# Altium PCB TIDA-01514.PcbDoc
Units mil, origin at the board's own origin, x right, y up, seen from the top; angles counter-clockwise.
Board outline 2800 x 2500 mil, 2 copper layers (Top Layer, Bottom Layer), stack 61.6 mil thick; 63 components, 22 nets, 133 pads, 71 vias.
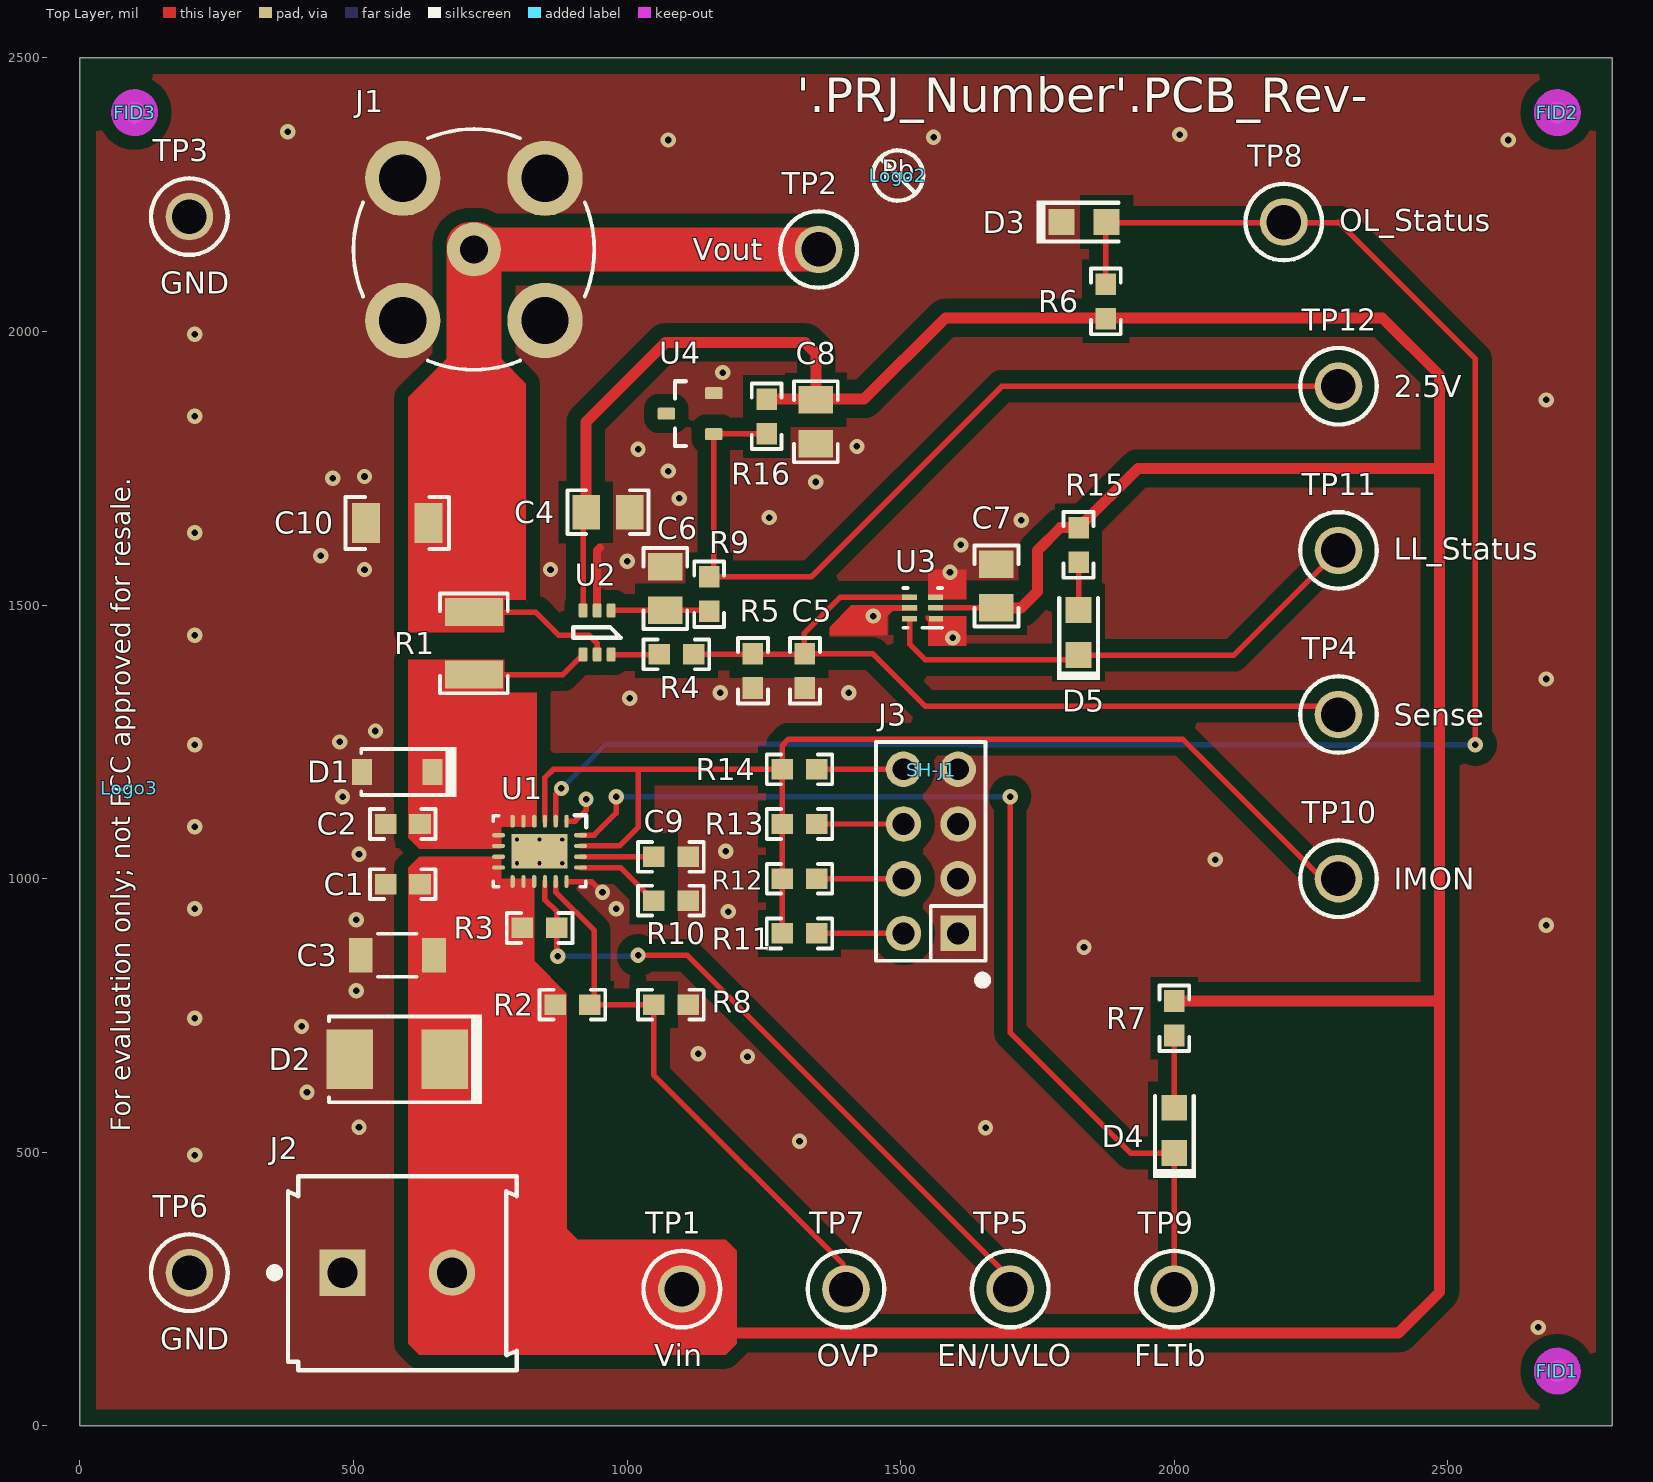
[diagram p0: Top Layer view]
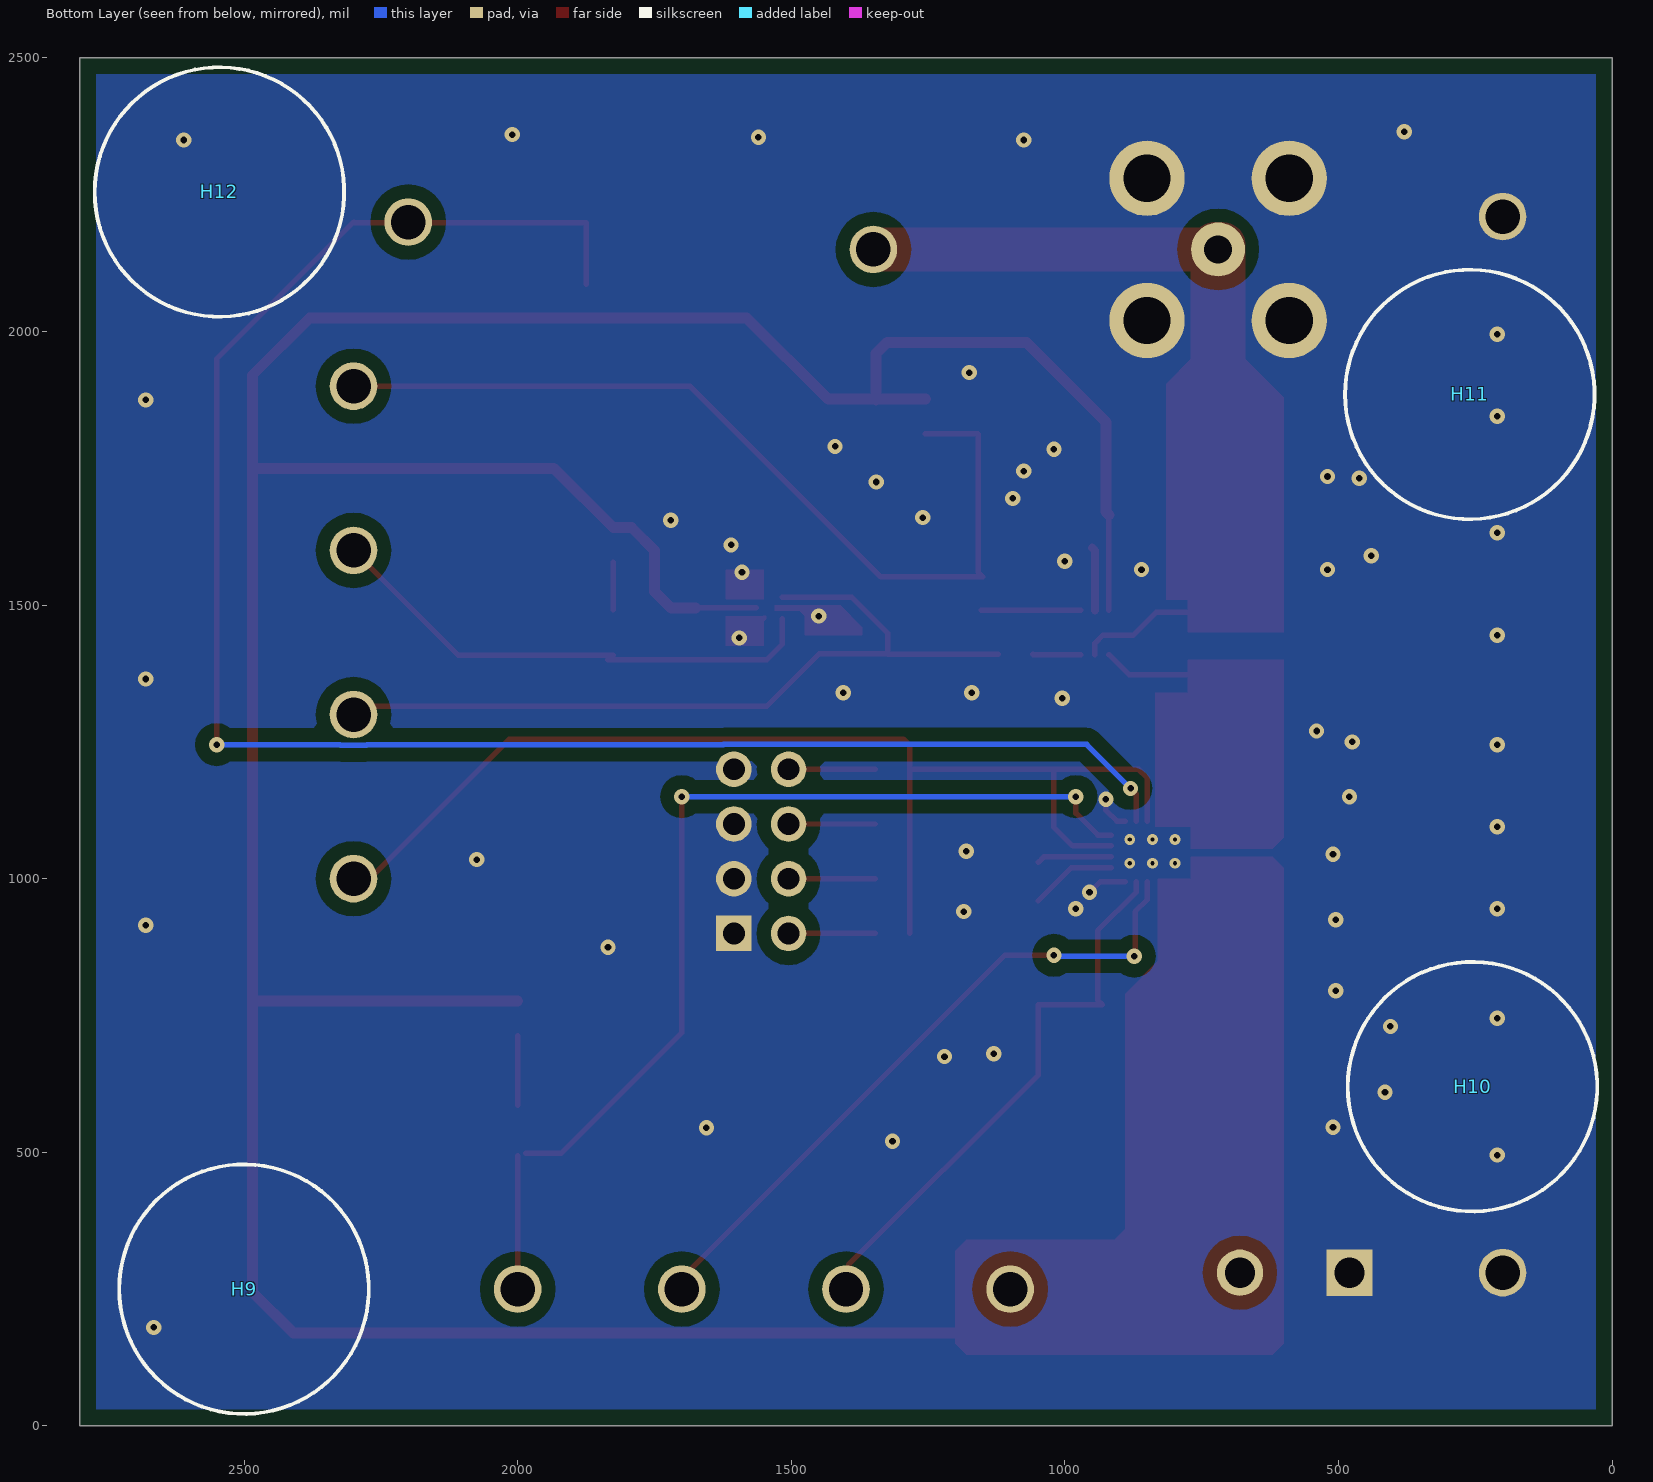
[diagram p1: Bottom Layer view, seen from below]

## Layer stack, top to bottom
Top Solder: solder mask 0.4, Solder Resist, Dk 3.5
Top Layer: signal copper 2.8
Dielectric1: core 56, FR-4, Dk 4.8
Bottom Layer: signal copper 2.8
Bottom Solder: solder mask 0.4, Solder Resist, Dk 3.5

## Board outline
0,0 0,2500 2800,2500 2800,0

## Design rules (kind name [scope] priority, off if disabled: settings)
AcuteAngle [All] p1: minimum=4.50000000000000E+0001 checktracksonly=FALSE
AssemblyTestPointUsage [All] p1: valid=2
BoardOutlineClearance BoardOutlineClearance_MountingHoles [OnCopper and InComponentClass('Mounting Holes')] p1: gap=40 ignorepadtopadclearanceinfootprint=FALSE
BoardOutlineClearance BoardOutlineClearance_Poly [OnCopper and IsPoly] p2: gap=25 ignorepadtopadclearanceinfootprint=FALSE
BoardOutlineClearance [OnCopper and Not InComponentClass('Logo') and not InComponentClass('FiducialMark') and not InRegion(1000,500,4000,800) and not InPoly] p3: gap=75 ignorepadtopadclearanceinfootprint=FALSE
Clearance Clearance_Keepouts [((IsTrack Or IsArc) And Not InPoly) And IsFree and IsKeepOut vs ((IsTrack Or IsArc) And Not InPoly) And IsFree and IsKeepOut] p1: gap=0 ignorepadtopadclearanceinfootprint=FALSE
Clearance Clearance_Poly [InPolygon] p2: gap=25 ignorepadtopadclearanceinfootprint=FALSE except(0: Arc-Hole Track-Hole SMDPad-Hole THPad-Hole Via-Hole Fill-Hole Poly-Hole Region-Hole Text-Hole)
Clearance Clearance_FiducialMark [IsKeepOut and InComponentClass('FiducialMark') vs IsPad and InComponentClass('FiducialMark')] p3: gap=0 ignorepadtopadclearanceinfootprint=FALSE
Clearance [All] p4: gap=7.87 ignorepadtopadclearanceinfootprint=FALSE except(0: Arc-Hole Track-Hole SMDPad-Hole THPad-Hole Via-Hole Fill-Hole Poly-Hole Region-Hole Text-Hole)
ComponentClearance ComponentClearance_MountingHoles_FiducialMarks [InComponentClass('Mounting Holes') vs InComponentClass('FiducialMark')] p1: gap=50 collisioncheckmode=3 verticalgap=10 showdistances=FALSE
ComponentClearance ComponentClearance_Shunt [InComponentClass('Header') vs InComponentClass('Shunt')] p2: gap=0 collisioncheckmode=3 verticalgap=0 showdistances=FALSE
ComponentClearance ComponentClearance_Logo [InComponentClass('Logo')] p3: gap=50 collisioncheckmode=3 verticalgap=10 showdistances=FALSE
ComponentClearance ComponentClearance_ScrewToNut [(HasFootprint('NY PMS 440 0025 PH')) vs (HasFootprint('Keystone_1902C'))] p4: gap=5 collisioncheckmode=3 verticalgap=10 showdistances=FALSE
ComponentClearance ComponentClearance_MountingHoles [InComponentClass('Mounting Holes')] p5: gap=250 collisioncheckmode=3 verticalgap=100000 showdistances=FALSE
ComponentClearance ComponentClearance_SmallPassives [HasFootprint('0201*') or HasFootprint('0402*') or HasFootprint('0508') or HasFootprint('0603*') or HasFootprint('0612') or HasFootprint('0805*') or HasFootprint('0815*') or HasFootprint('0830*') or HasFootprint('1206*') or HasFootprint('1210*') or HasFootprint('1808*') or HasFootprint('1812*') or HasFootprint('1825*') or HasFootprint('2010*') or HasFootprint('2220*') or HasFootprint('2225*') or HasFootprint('2512*') or HasFootprint('2728*') or HasFootprint('3518*') vs HasFootprint('0201*') or HasFootprint('0402*') or HasFootprint('0508') or HasFootprint('0603*') or HasFootprint('0612') or HasFootprint('0805*') or HasFootprint('0815*') or HasFootprint('0830*') or HasFootprint('1206*') or HasFootprint('1210*') or HasFootprint('1808*') or HasFootprint('1812*') or HasFootprint('1825*') or HasFootprint('2010*') or HasFootprint('2220*') or HasFootprint('2225*') or HasFootprint('2512*') or HasFootprint('2728*') or HasFootprint('3518*')] p6: gap=14.96 collisioncheckmode=3 verticalgap=10 showdistances=FALSE
ComponentClearance ComponentClearance_THtoSMT [IsThruComponent vs IsSMTComponent] p7: gap=40 collisioncheckmode=3 verticalgap=30 showdistances=FALSE
ComponentClearance ComponentClearance_THtoTH [IsThruComponent vs IsThruComponent] p8: gap=30 collisioncheckmode=3 verticalgap=30 showdistances=FALSE
ComponentClearance [All] p9: gap=30 collisioncheckmode=3 verticalgap=10 showdistances=FALSE
DiffPairsRouting [All] p1: maxlimit=100 minlimit=10 mostfreqgap=10 toplayer_minwidth=15 toplayer_maxwidth=15 toplayer_prefwidth=15 bottomlayer_minwidth=15 bottomlayer_maxwidth=15 bottomlayer_prefwidth=15 maxuncoupledlength=1000
FabricationTestPointUsage TestPointUsage [All] p1: valid=2 allowmultiple=FALSE
FabricationTestpoint Testpoint [All] p1: side=3 testpointundercomponent=TRUE minsize=40 maxsize=100 preferedsize=60 minholesize=0 maxholesize=40 preferedholesize=32 testpointgrid=1 allowsidetop=TRUE allowsidebottom=TRUE usegrid=TRUE gridtolerance=0.01
FanoutControl Fanout_LCC [IsLCC] p1: bgadir=Out bgaviamode=Centered fanoutstyle=Auto fanoutdirection=Alternating viagrid=1 // Fanout_LCC (Default Rule)
FanoutControl Fanout_BGA [IsBGA] p2: bgadir=Out bgaviamode=Centered fanoutstyle=Auto fanoutdirection=Alternating viagrid=1 // Fanout_BGA (Default Rule)
FanoutControl Fanout_Default [All] p4: bgadir=Out bgaviamode=Centered fanoutstyle=Auto fanoutdirection=Alternating viagrid=1 // Fanout_Default (Default Rule)
FanoutControl Fanout_Small [(CompPinCount < 5)] p5: bgadir=Out bgaviamode=Centered fanoutstyle=Auto fanoutdirection=OutThenIn viagrid=1 // Fanout_Small (Default Rule)
HoleSize [All] p1: absolutevalues=TRUE maxlimit=251 minlimit=7.87 maxpercent=80.000 minpercent=20.000
MinimumAnnularRing MinimumAnnularRing_ThermalPadVias [IsVia and InAnyComponent] p1: minimumring=5.91
MinimumAnnularRing [All] p2: minimumring=8
MinimumSolderMaskSliver MinimumSolderMaskSliver_Logo [InComponentClass('Logo') vs InComponentClass('Logo')] p1: minsoldermaskwidth=0.7
MinimumSolderMaskSliver [All] p2: minsoldermaskwidth=3.94
PlaneConnect [All] p1: planeconnectstyle=Direct reliefexpansion=10 reliefentries=4 reliefconductorwidth=10 reliefairgap=10
PolygonConnect [All] p1: connectstyle=Direct reliefconductorwidth=10 reliefentries=4 polygonreliefangle="90 Angle" airgapwidth=10
RoutingVias ThermalPadVias [IsVia and InAnyComponent] p1: holewidth=7.87 width=19.68 viastyle="Through Hole" minholewidth=7.87 minwidth=19.68 maxholewidth=12.99 maxwidth=23.62
RoutingVias [All] p2: holewidth=16 width=34 viastyle="Through Hole" minholewidth=7.87 minwidth=26 maxholewidth=40 maxwidth=65
SilkToBoardRegionClearance [Not ((IsComment or IsDesignator) And (Hide <> 'False')) and not InRegion(1000,500,4000,800)] p1:
SilkToSilkClearance SilkToSilkClearance_Pb-FreeLogo [(HasFootprint('Pb-Free_Overlay_Medium') OR HasFootprint('Pb-Free_Overlay_Small')) vs (HasFootprint('Pb-Free_Overlay_Medium') OR HasFootprint('Pb-Free_Overlay_Small'))] p1: silktosilkclearance=0
SilkToSilkClearance [All] p2: silktosilkclearance=4
SilkToSolderMaskClearance SilkToComponentPadClearance [(IsPad or IsFill or IsRegion) and InAnycomponent] p1: minsilkscreentomaskgap=3.5 clearancetoexposedcopper=TRUE
SilkToSolderMaskClearance "Silk to Solder Mask Opening" [All] p2: minsilkscreentomaskgap=4 clearancetoexposedcopper=FALSE
SolderMaskExpansion [All] p1: expansion=1.97
Width [All] p1: maxlimit=100 minlimit=6 preferedwidth=10 checkconnectedcopper=TRUE
15 further rules are at their usual default settings.

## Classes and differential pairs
component class Shunt: SH-J1
component class TIDA-01514: C1 C2 C3 C4 C5 C6 C7 C8 C9 C10 D1 D2 D3 D4 D5 J1 J2 J3 R1 R2 R3 R4 R5 R6 R7 R8 R9 R10 R11 R12 R13 R14 R15 R16 TP1 TP2 TP3 TP4 TP5 TP6 TP7 TP8 TP9 TP10 TP11 TP12 U1 U2 U3 U4
component class Header: J3
component class AssemblyNote: ZZ2 ZZ3 ZZ4
component class FiducialMark: FID1 FID2 FID3
component class TIDA-01514_Hardware: FID1 FID2 FID3 H9 H10 H11 H12 Logo2 Logo3 SH-J1 ZZ2 ZZ3 ZZ4

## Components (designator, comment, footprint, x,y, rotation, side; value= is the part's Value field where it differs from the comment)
C1 "CMP-0007144-2" 0603 590,990 r180 top value=0.1uF
C2 "CMP-0007136-2" 0603 590,1100 r180 top value=1uF
C3 "CMP-0008968-2" 1206_180 580,860 r180 top value=2.2uF
C4 "CMP-0007886-2" 0805_HV 965,1670 r180 top value=0.1uF
C5 "0603ZC103KAT2A" 0603 1325,1380 r270 top value=0.01uF
C6 "CMP-0007886-2" 0805_HV 1070,1530.35 r270 top value=0.1uF
C7 "CMP-0007886-2" 0805_HV 1675,1535 r270 top value=0.1uF
C8 "CMP-0007886-2" 0805_HV 1345,1835 r90 top value=0.1uF
C9 "GRM188R71E102KA01D" 0603 1080,1040 r0 top value=1000pF
C10 "C3216X7R1E475K085AB" 1206 580,1650 r180 top value=4.7uF
D1 "CMP-0028546-1" SOD-123FL 580,1195 r180 top value=20V
D2 "SMBJ15A-13-F" SMB 580,670 r180 top value=15V
D3 "CMP-0002829-2" LED_LTST-C170_Red 1835,2200 r180 top value=Red
D4 "CMP-0002829-2" LED_LTST-C170_Red 2000,540 r270 top value=Red
D5 "CMP-0002829-2" LED_LTST-C170_Red 1825,1450 r270 top value=Red
FID1 "Fiducial" Fiducial10-20 2700,100 r0 top
FID2 "Fiducial" Fiducial10-20 2700,2400 r0 top
FID3 "Fiducial" Fiducial10-20 100,2400 r0 top
H9 "SJ-5303 (CLEAR)" Bumpon_SJ5003Transparent 2500,250 r180 bottom
H10 "SJ-5303 (CLEAR)" Bumpon_SJ5003Transparent 255,620 r180 bottom
H11 "SJ-5303 (CLEAR)" Bumpon_SJ5003Transparent 260,1885 r180 bottom
H12 "SJ-5303 (CLEAR)" Bumpon_SJ5003Transparent 2545,2255 r180 bottom
J1 "112404" Amphenol_112404 720,2150 r0 top
J2 "CMP-0054973-1" TEC_282841-2 580,280 r0 top
J3 "PEC04DAAN" CONN_PEC04DAAN 1555,1050 r90 top
Logo2 "Pb-Free Symbol" Pb-Free_Overlay_Small 1495,2285 r0 top
Logo3 "FCC disclaimer" FCC_disclaimer 90,1165 r90 top
R1 "MCR25JZHFLR180" 1210 720,1430 r90 top value=0.18
R2 "CMP-0022620-2" 0603 900,770 r180 top value=82.5k
R3 "CMP-0022436-2" 0603 840,910 r180 top value=475k
R4 "CMP-0021998-2" 0603 1090,1410 r0 top value=10.0k
R5 "RT0603DRE071K35L" 0603 1230,1380 r90 top value=1.35k
R6 "CMP-0022456-2" 0603 1875,2055 r90 top value=4.75k
R7 "CMP-0022456-2" 0603 2000.03,745 r90 top value=4.75k
R8 "CMP-0022098-2" 0603 1080,770 r180 top value=18.7k
R9 "CRCW060310R0FKEAHP" 0603 1150,1520 r270 top value=10.0
R10 "CMP-0022536-2" 0603 1080,960 r180 top value=61.9k
R11 "CRCW060315K8FKEA" 0603 1315,900 r180 top value=15.8k
R12 "CRCW060321K0FKEA" 0603 1315,1000 r180 top value=21.0k
R13 "CRCW060331K6FKEA" 0603 1315,1100 r180 top value=31.6k
R14 "CMP-0022536-2" 0603 1315,1200 r180 top value=61.9k
R15 "CMP-0022456-2" 0603 1825,1610 r90 top value=4.75k
R16 "CMP-0022456-2" 0603 1255,1845 r90 top value=4.75k
SH-J1 "969102-0000-DA" SNT-100-BK-G 1557,1198 r180 top value=1x2
TP1 "Vin" Keystone5010 1100,250 r0 top
TP2 "Vout" Keystone5010 1350,2150 r0 top
TP3 "GND" Keystone5011 200,2210 r0 top
TP4 "Sense" Keystone5012 2300,1300 r0 top
TP5 "EN/UVLO" Keystone5012 1700,250 r0 top
TP6 "GND" Keystone5011 200,280 r0 top
TP7 "OVP" Keystone5012 1400,250 r0 top
TP8 "OL_Status" Keystone5012 2200,2200 r0 top
TP9 "FLTb" Keystone5012 2000,250 r0 top
TP10 "IMON" Keystone5012 2300,1000 r0 top
TP11 "LL_Status" Keystone5012 2300,1600 r0 top
TP12 "2.5V" Keystone5010 2300,1900 r0 top
U1 "TPS25940AQRVCRQ1" RVC0020A 840,1050 r270 top
U2 "INA211BQDCKRQ1" DCK0006A_L 945,1450 r270 top
U3 "TPS3710DSER" DSE0006A 1540,1495 r180 top
U4 "LM4040QCIM3X2.5/NOPB" DBZ0003A_L 1115,1850 r180 top
ZZ2 "These assemblies are ESD sensitive, ESD precautions shall be observed." AssemblyNote 185,3829.11 r0 top
ZZ3 "These assemblies must be clean and free from flux and all contaminants. Use of no clean flux is not acceptable." AssemblyNote 185,3740.56 r0 top
ZZ4 "These assemblies must comply with workmanship standards IPC-A-610 Class 2, unless otherwise specified." AssemblyNote 185,3652 r0 top

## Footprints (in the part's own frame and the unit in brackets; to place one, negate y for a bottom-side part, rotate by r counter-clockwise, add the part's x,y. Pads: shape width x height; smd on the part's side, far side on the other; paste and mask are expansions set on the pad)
0603 [mm] "0603 from SM-752 data"
  rect 1x0.95 smd: 1(-0.8,0) 2(0.8,0)
  silkscreen extent -1.52,-0.69 1.52,0.69, body extent -0.87,-0.47 0.87,0.47, height 1
0805_HV [mil] "0805 with 30mil clearance between pads"
  rect 50x63 smd: 1(-40,0) 2(40,0)
  silkscreen extent -74,-40 74,40, body extent -43,-29 43,29, height 57
1206 [mm] "1206 from SM-752 data"
  rect 1.3x1.85 smd: 1(-1.45,0) 2(1.45,0)
  silkscreen extent -2.4,-1.21 2.4,1.21, body extent -1.7,-0.9 1.7,0.9, height 1.35
1206_180 [mm] "1206_180"
  rect 1.1x1.6 smd: 1(-1.7,0) 2(1.7,0)
  silkscreen extent -0.9,-1 0.9,1, body extent -1.75,-0.95 1.75,0.95, height 1.8
1210 [mm] "1210 from SM-752 data"
  rect 1.3x2.7 smd: 1(-1.45,0) 2(1.45,0)
  silkscreen extent -2.32,-1.57 2.32,1.57, body extent -1.7,-1.35 1.7,1.35, height 1.35
Amphenol_112404 [mm] "BNC footprint, pins compatible with Amp 5413631-2"
  round 2.5 hole 1.3: 1(0,0)
  round 3.5 hole 2.2: 2(-3.3,3.3) 3(3.3,3.3) 4(3.3,-3.3) 5(-3.3,-3.3)
  silkscreen extent -5.59,-5.59 5.59,5.59, body extent -5.5,-5.5 5.5,5.5, height 13.7
AssemblyNote [mil] "Assembly Note"
Bumpon_SJ5003Transparent [mil] "3M Hemispherical Bumpon transparent"
  round 1 on Mech4: 0(0,0)
  silkscreen extent -228,-228 228,228, body extent -219,-219 219,219, height 197
CONN_PEC04DAAN [mm] "SULLINS"
  rect 1.65x1.65 hole 1.016 mask+0: 1(-3.81,-1.27)
  round 1.65 hole 1.016 mask+0: 2(-3.81,1.27) 3(-1.27,-1.27) 4(-1.27,1.27) 5(1.27,-1.27) 6(1.27,1.27) 7(3.81,-1.27) 8(3.81,1.27)
  silkscreen extent -6.18,-2.6 5.08,2.54, body extent -5.08,-2.54 5.08,2.54, height 8.38
DBZ0003A_L [mm] "SOT23, 3-Leads, Body 2.9x1.3mm, Pitch 0.95mm, Lead Span 2.4mm, IPC High Density"
  rrect18% 0.8x0.55 smd: 1(-1.1,0.95) 2(-1.1,-0.95) 3(1.1,0)
  silkscreen extent 0.2,-1.5 0.7,1.5, body extent -1.26,-1.46 1.26,1.46, height 0.98
DCK0006A_L [mm] "SOT23, 6-Leads, Body 2x1.3mm, Pitch 0.65mm, Lead Span 2.1mm, IPC High Density"
  rrect25% 0.65x0.4 smd: 1(-1.025,0.65) 2(-1.025,0) 3(-1.025,-0.65) 4(1.025,-0.65) 5(1.025,0) 6(1.025,0.65)
  silkscreen extent -0.25,-1.1 0.25,1.1, body extent -1.14,-1 1.14,1, height 0.95
DSE0006A [mm] "TI recommended land pattern"
  rect 0.66x0.25 smd: 1(-0.62,0.5)
  rect 0.7x0.25 smd: 2(-0.6,0) 3(-0.6,-0.5) 4(0.6,-0.5) 5(0.6,0) 6(0.6,0.5)
  Top Layer region: -0.3,0.625 -0.25,0.625 -0.15,0.525 -0.15,0.375 -0.3,0.375
  silkscreen extent -0.9,-0.92 0.9,0.92, body extent -0.77,-0.77 0.77,0.77, height 0.8
FCC_disclaimer [mil]
Fiducial10-20 [mm]
  round 1 smd mask+0.5: 1(0,0)
  Top Layer keep-out circle w1.178: c0,0 r0.5
Keystone5010 [mil] "Keystone Multipurpose loops"
  round 87 hole 63: 1(0,0)
  silkscreen extent -70,-70 70,70, body extent -63,-63 63,62, height 319
Keystone5011 [mil] "Keystone Multipurpose loops"
  round 87 hole 63: 1(0,0)
  silkscreen extent -70,-70 70,70, body extent -63,-63 63,62, height 319
Keystone5012 [mil] "Keystone Multipurpose loops"
  round 87 hole 63: 1(0,0)
  silkscreen extent -70,-70 70,70, body extent -63,-63 63,62, height 319
LED_LTST-C170_Red [mm] "LITE-ON"
  rect 1.2x1.2 smd: 1(-1.05,0) 2(1.05,0)
  silkscreen extent -1.6,-1 2.2,1, body extent -1.05,-0.67 1.05,0.67, height 1.1
Pb-Free_Overlay_Small [mil]
  silkscreen extent -46,-46 46,46
RVC0020A [mm] "TI"
  oval 0.6x0.2 smd: 1(-1.4,1.25) 2(-1.4,0.75) 3(-1.4,0.25) 4(-1.4,-0.25) 5(-1.4,-0.75) 6(-1.4,-1.25) 11(1.4,-1.25) 12(1.4,-0.75) 13(1.4,-0.25) 14(1.4,0.25) 15(1.4,0.75) 16(1.4,1.25)
  oval 0.2x0.6 smd: 7(-0.75,-1.9) 8(-0.25,-1.9) 9(0.25,-1.9) 10(0.75,-1.9) 17(0.75,1.9) 18(0.25,1.9) 19(-0.25,1.9) 20(-0.75,1.9)
  rect 1.6x2.6 smd paste-1: 21(0,0)
  silkscreen extent -1.68,-2.15 1.65,2.18, body extent -1.55,-2.05 1.55,2.05, height 0.8
SMB [mil] "Molded Diode, 2-Leads, Body 5.4x3.6mm, IPC Medium Density, based on OnSemi component dimensions"
  rect 85x107.99 smd: 1(-87.01,0) 2(87.01,0)
  silkscreen extent -155,-82 125,82, body extent -106,-71 106,71, height 91
SNT-100-BK-G [mil] "Samtec STEP model"
  round 1 on Mech3: 0(0,0)
  body extent -100,-50 100,50, height 344
SOD-123FL [mm] "Copied from SOD-123"
  rect 0.915x1.22 smd: 1(-1.637,0) 2(1.637,0)
  silkscreen extent -2.74,-1.16 1.68,1.16, body extent -1.9,-0.9 1.9,0.9, height 1
TEC_282841-2 [mm] "TE Connectivity"
  rect 2.15x2.15 hole 1.4: 1(-2.54,0)
  round 2.15 hole 1.4: 2(2.54,0)
  silkscreen extent -5.9,-4.52 5.55,4.47, body extent -5.08,-4.52 5.58,4.48, height 15.2

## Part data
C1: "CAP, CERM, 0.1 uF, 50 V, +/- 10%, X7R, 0603", Cap_Case=0603, Manufacturer=MuRata, PartNumber=GCM188R71H104KA57D, Supplier Part Number 1=490-4779-1-ND, TempCo=X7R, Tolerance_%=10%, Value1="0.02 ohm", Value2=50V, ValueDisplayed=0.1uF
C2: "CAP, CERM, 1 uF, 16 V, +/- 10%, X7R, AEC-Q200 Grade 1, 0603", Cap_Case=0603, Manufacturer=MuRata, PartNumber=GCM188R71C105KA64D, Supplier Part Number 1=490-5241-6-ND, TempCo=X7R, Tolerance_%=10%, Value1=Unknown, Value2=16V, ValueDisplayed=1uF
C3: "CAP, CERM, 2.2 uF, 50 V, +/- 10%, X7R, 1206", Cap_Case=1206, Manufacturer=MuRata, PartNumber=GRM31CR71H225KA88L, Supplier Part Number 1=490-3367-1-ND, TempCo=X7R, Tolerance_%=10%, Value1=Unknown, Value2=50V, ValueDisplayed=2.2uF
C4 C6 C7 C8: "CAP, CERM, 0.1 uF, 100 V, +/- 10%, X7R, 0805", Cap_Case=0805, Manufacturer=TDK, PartNumber=C2012X7R2A104K125AA, Supplier Part Number 1=445-1418-1-ND, TempCo=X7R, Tolerance_%=10%, Value1="0.020726 ohm", Value2=100V, ValueDisplayed=0.1uF
C5: library part CMP-0006814-2, "CAP, CERM, 0.01 uF, 10 V, +/- 10%, X7R, 0603", Cap_Case=0603, Manufacturer=AVX, Supplier Part Number 1=478-7938-2-ND, TempCo=X7R, Tolerance_%=10%, Value1=Unknown, Value2=10V, ValueDisplayed=0.01uF
C9: library part CMP-0007402-2, "CAP, CERM, 1000 pF, 25 V, +/- 10%, X7R, 0603", Cap_Case=0603, Manufacturer=MuRata, Supplier Part Number 1=GRM188R71E102KA01D-ND, TempCo=X7R, Tolerance_%=10%, Value1=Unknown, Value2=25V, ValueDisplayed=1000pF
C10: library part CMP-0008693-2, "CAP, CERM, 4.7 uF, 25 V, +/- 10%, X7R, 1206", Cap_Case=1206, Manufacturer=TDK, Supplier Part Number 1=445-14797-1-ND, TempCo=X7R, Tolerance_%=10%, Value1=Unknown, Value2=25V, ValueDisplayed=4.7uF
D1: "Diode, Schottky, 20 V, 1 A, SOD-123FL", Manufacturer="ON Semiconductor", PartNumber=MBR120LSFT1G, Supplier Part Number 1=MBR120LSFT1GOSCT-ND, Value1=1A, Value2=0.45V
D2: library part CMP-0005545-2, "Diode, TVS, Uni, 15 V, 24.4 Vc, SMB", Manufacturer="Diodes Inc.", Power_W=5W, Supplier Part Number 1=SMBJ15A-FDICT-ND
D3 D4 D5: "LED, Red, SMD", Color=red, Manufacturer=Lite-On, PartNumber=LTST-C170KRKT, Supplier Part Number 1=160-1415-1-ND, Value1=W, Value2=2V
FID1 FID2 FID3: library part CMP-0077181-1, "Fiducial mark.  There is nothing to buy or mount.", Manufacturer=N/A
H9 H10 H11 H12: library part CMP-0003620-1, "Bumpon, Hemisphere, 0.44 X 0.20, Clear", Manufacturer=3M, Supplier Part Number 1=SJ5303-7-ND
J1: library part CMP-0055424-1, "Connector, TH, BNC", Manufacturer="Amphenol Connex", Supplier Part Number 1=ACX1051-ND
J2: "Terminal Block, 2x1, 5.08mm, TH", Manufacturer="TE Connectivity", PartNumber=282841-2, Supplier Part Number 1=A98342-ND
J3: library part CMP-0054542-1, "Header, 100mil, 4x2, Tin, TH", Color=Black, Current_A=3A, Manufacturer="Sullins Connector Solutions", Supplier Part Number 1=S2012E-04-ND, Voltage_V=1.8kV
Logo2: library part CMP-0074839-1
Logo3: library part CMP-0074847-1, "FCC_disclaimer"
R1: library part CMP-0015173-2, "RES, 0.18, 1%, 0.5 W, 1210", Manufacturer=Rohm, Power_W=500mW, Supplier Part Number 1=RHM.18SCT-ND, TempCo="200 ppm/C", Tolerance_%=1%, Value2=0.5W, Value_Code=R180, ValueDisplayed=0.18
R2: "RES, 82.5 k, 1%, 0.1 W, 0603", Manufacturer=Vishay-Dale, PartNumber=CRCW060382K5FKEA, Power_W=100mW, Supplier Part Number 1=541-82.5KHCT-ND, TempCo="100 ppm/C", Tolerance_%=1%, Value2=0.1W, Value_Code=82k5, ValueDisplayed=82.5k
R3: "RES, 475 k, 1%, 0.1 W, 0603", Manufacturer=Vishay-Dale, PartNumber=CRCW0603475KFKEA, Power_W=100mW, Supplier Part Number 1=541-475KHCT-ND, TempCo="100 ppm/C", Tolerance_%=1%, Value2=0.1W, Value_Code=475k
R4: "RES, 10.0 k, 1%, 0.1 W, 0603", Manufacturer=Vishay-Dale, PartNumber=CRCW060310K0FKEA, Power_W=100mW, Supplier Part Number 1=541-10.0KHCT-ND, TempCo="100 ppm/C", Tolerance_%=1%, Value2=0.1W, Value_Code=10k0, ValueDisplayed=10.0k
R5: library part CMP-0024818-2, "RES, 1.35 k, 0.5%, 0.1 W, 0603", Manufacturer="Yageo America", Power_W=100mW, TempCo="50 ppm/C", Tolerance_%=0.5%, Value2=0.1W, Value_Code=1k35, ValueDisplayed=1.35k
R6 R7 R15 R16: "RES, 4.75 k, 1%, 0.1 W, 0603", Manufacturer=Vishay-Dale, PartNumber=CRCW06034K75FKEA, Power_W=100mW, Supplier Part Number 1=541-4.75KHCT-ND, TempCo="100 ppm/C", Tolerance_%=1%, Value2=0.1W, Value_Code=4k75, ValueDisplayed=4.75k
R8: "RES, 18.7 k, 1%, 0.1 W, 0603", Manufacturer=Vishay-Dale, PartNumber=CRCW060318K7FKEA, Power_W=100mW, Supplier Part Number 1=541-18.7KHCT-ND, TempCo="100 ppm/C", Tolerance_%=1%, Value2=0.1W, Value_Code=18k7, ValueDisplayed=18.7k
R9: library part CMP-0022004-2, "RES, 10.0, 1%, 0.25 W, 0603", Manufacturer=Vishay-Dale, Power_W=250mW, Supplier Part Number 1=541-10.0SCT-ND, TempCo="100 ppm/C", Tolerance_%=1%, Value2=0.25W, Value_Code=10R0, ValueDisplayed=10.0
R10 R14: "RES, 61.9 k, 1%, 0.1 W, 0603", Manufacturer=Vishay-Dale, PartNumber=CRCW060361K9FKEA, Power_W=100mW, Supplier Part Number 1=541-61.9KHCT-ND, TempCo="100 ppm/C", Tolerance_%=1%, Value2=0.1W, Value_Code=61k9, ValueDisplayed=61.9k
R11: library part CMP-0022068-2, "RES, 15.8 k, 1%, 0.1 W, 0603", Manufacturer=Vishay-Dale, Power_W=100mW, Supplier Part Number 1=541-15.8KHCT-ND, TempCo="100 ppm/C", Tolerance_%=1%, Value2=0.1W, Value_Code=15k8, ValueDisplayed=15.8k
R12: library part CMP-0022212-2, "RES, 21.0 k, 1%, 0.1 W, 0603", Manufacturer=Vishay-Dale, Power_W=100mW, Supplier Part Number 1=541-21.0KHCT-ND, TempCo="100 ppm/C", Tolerance_%=1%, Value2=0.1W, Value_Code=21k0, ValueDisplayed=21.0k
R13: library part CMP-0022330-2, "RES, 31.6 k, 1%, 0.1 W, 0603", Manufacturer=Vishay-Dale, Power_W=100mW, Supplier Part Number 1=541-31.6KHCT-ND, TempCo="100 ppm/C", Tolerance_%=1%, Value2=0.1W, Value_Code=31k6, ValueDisplayed=31.6k
SH-J1: library part CMP-0003614-1, "Shunt, 100mil, Gold plated, Black", Alternate Manufacturer=Samtec, Alternate PartNumber=SNT-100-BK-G, Manufacturer=3M, Supplier Part Number 1=3M9580-ND
TP1 TP2 TP12: library part CMP-0055147-1, "Test Point, Multipurpose, Red, TH", Color=Red, Manufacturer=Keystone, PartNumber=5010, Supplier Part Number 1=36-5010-ND
TP3 TP6: library part CMP-0055148-1, "Test Point, Multipurpose, Black, TH", Color=Black, Manufacturer=Keystone, PartNumber=5011, Supplier Part Number 1=36-5011-ND
TP4 TP5 TP7 TP8 TP9 TP10 TP11: library part CMP-0055149-1, "Test Point, Multipurpose, White, TH", Color=White, Manufacturer=Keystone, PartNumber=5012, Supplier Part Number 1=36-5012-ND
U1: library part CMP-0076737-1, "2.7V to 18V eFuse with Integrated Short-to-Battery Protection, RVC0020A (WQFN-20)", Alternate Manufacturer="Texas Instruments", Alternate PartNumber=TPS25940AQRVCTQ1
U2: library part CMP-0076880-1, "Automotive-Grade, Voltage Output, Low- or High-Side Measurement, Bidirectional, Zero-Drift Series, Current-Shunt Monitor, DCK0006A (SOT-SC70-6)", Alternate Manufacturer="Texas Instruments"
U3: library part CMP-0077206-1, "Automotive Grade Wide VIN Voltage Detector, DSE0006A (WSON-6)", Alternate Manufacturer="Texas Instruments", PartNumber=TPS3710QDSERQ1
U4: library part CMP-0076734-2, "Precision Micropower Shunt Voltage Reference, DBZ0003A (SOT-23-3)", Alternate Manufacturer="Texas Instruments"
ZZ2: library part CMP-0077236-1
ZZ3: library part CMP-0077237-1
ZZ4: library part CMP-0077238-1

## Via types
v1: diameter 28, hole 12, Top Layer to Bottom Layer, 65 vias
v2: diameter 19.68, hole 7.87, Top Layer to Bottom Layer, 6 vias

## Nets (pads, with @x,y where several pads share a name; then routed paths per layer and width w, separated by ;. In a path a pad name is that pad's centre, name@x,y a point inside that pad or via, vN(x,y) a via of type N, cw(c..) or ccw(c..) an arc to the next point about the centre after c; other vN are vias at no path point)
+2.5V: R9.1 R16.1 TP12.1 U4.1 | length 1654.7
  Top Layer w10: U4.1 1158.31,1559.8 R9.1 1336.5,1551.5 1685,1900 TP12.1 ; U4.1@1159.21,1813.5 R16.1
\FLT: D4.2 TP9.1 U1.20 | length 1853.1
  Top Layer w10: U1.20 939.53,1079.53 980,1120 v1(980,1150) ; v1(1700,1150) 1700,718.66 1920,498.66 D4.2@1985,498.66 ; TP9.1@2000,280 D4.2@2000,493.66
  Bottom Layer w10: v1(980,1150) v1(1700,1150)
GND: C1.2 C2.2 C3.2 C4.1 C5.2 C6.1 C7.1 C8.1 C9.2 C10.2 D1.2 D2.2 D3.2 J1.2 J1.3 J1.4 J1.5 J2.1 J3.1 J3.3 J3.5 J3.7 R5.1 R8.1 R10.1 TP3.1 TP6.1 U1.1 U1.16 U1.21 U2.2 U3.1 U3.3 U3.5 U4.2 | length 254.8
  Top Layer w10: U1.16 935.12,994.88 v1(955,975) ; U1.1 905.12,1105.12 925,1125 v1(925,1145)
  Top Layer w15: U2.2 945,1600 950,1605
  other v1: 2665,180 210,495 1315,520 1655,545 510,546 415,610 1220,675 1130,680 405,730 210,745 505,795 1835,875 2680,915 505,925 1185,940 210,945 980,945 2075,1035 510,1045 1180,1050 210,1095 480,1150 210,1245 475,1250 540,1270 1005,1330 1170,1340 1405,1340 2680,1365 1595,1440 210,1445 1450,1480 1590,1560 520,1565 860,1565 1000,1580 440,1590 1610,1610 210,1632 1720,1655 1260,1660 1095,1695 1345,1725 462,1732 520,1735 1075,1745 1020,1785 1420,1790 210,1845 2680,1875 1175,1925 210,1995 1075,2350 2610,2350 1560,2355 2010,2360 380,2365
  other v2: 798.66,1028.35 840,1028.35 881.34,1028.35 798.66,1071.65 840,1071.65 881.34,1071.65
NetC2_1: C2.1 D1.1 R1.1 U1.4 U1.5 U1.6 U1.7 U1.8 U2.4 | length 214.6
  Top Layer w10: R1.1 882.68,1372.91 U2.4
NetC6_2: C6.2 R9.2 U2.1 | length 182.6
  Top Layer w10: U2.1 R9.2@1153.15,1490.35
NetC9_1: C9.1 U1.18 | length 137.9
  Top Layer w10: U1.18 1038.35,1040.16 C9.1@1048.5,1030
NetD3_1: D3.1 R6.2 TP8.1 U1.2 | length 3363.2
  Top Layer w10: U1.2 869.53,1154.53 v1(880,1165) ; R6.2 1875,2198.66 2298.66,2198.66 ; 2300,2200 2550,1950 v1(2550,1245)
  Bottom Layer w10: v1(880,1165) 960.35,1245.35 1623.79,1245.35 1624.14,1245 2275.28,1245 2276.65,1243.63 2323.35,1243.63 2324.72,1245 v1(2550,1245)
NetD4_1: D4.1 R7.1 | length 127.2
  Top Layer w10: D4.1@2000,586.34 R7.1
NetD5_1: D5.1 R15.1 | length 87.2
  Top Layer w10: D5.1 R15.1
NetD5_2: D5.2 TP11.1 U3.6 | length 931.4
  Top Layer w10: U3.6 1516.38,1428.62 1545,1400 D5.2@1835,1400 ; D5.2 2108.66,1408.66 TP11.1
NetJ3_2: J3.2 R11.1 | length 158.5
  Top Layer w10: R11.1 J3.2
NetJ3_4: J3.4 R12.1 | length 158.5
  Top Layer w10: R12.1 J3.4
NetJ3_6: J3.6 R13.1 | length 158.5
  Top Layer w10: R13.1 J3.6
NetJ3_8: J3.8 R14.1 | length 158.5
  Top Layer w10: R14.1 J3.8
NetR2_1: R2.1 R8.2 TP7.1 U1.15 | length 1008.1
  Top Layer w10: U1.15 869.53,975.47 940,905 940,778.5 R2.1 R8.2 1048.5,641.5 1395,295 TP7.1@1395,280
NetR3_1: R3.1 TP5.1 U1.14 | length 1204.7
  Top Layer w10: U1.14 849.84,961.36 871.5,939.7 R3.1 871.5,858.5 v1(873.5,858.5) ; v1(1020,860) 1110,860 TP5.1@1690,280
  Bottom Layer w10: v1(873.5,858.5) 1018.5,858.5 v1(1020,860)
NetR4_1: R4.1 U2.6 | length 88.1
  Top Layer w10: U2.6 1058.15,1409.65 R4.1
NetR10_2: R10.2 U1.17 | length 158.7
  Top Layer w10: U1.17 988.03,1020.47 R10.2
NetR11_2: R11.2 R12.2 R13.2 R14.2 TP10.1 U1.3 U1.19 | length 2215.4
  Top Layer w10: U1.3 849.84,1184.84 865,1200 1020,1200 ; U1.19 985.84,1059.84 1020,1094 1020,1200 ; R11.2 R12.2 R13.2 R14.2 ; TP10.1 2270,1000 2015,1255 1295,1255 1283.5,1243.5 R14.2 ; 1020,1200 R14.2
Sense: C5.1 R4.2 R5.2 TP4.1 U3.4 | length 1482
  Top Layer w10: R4.2 1323.5,1410 1323.5,1448.5 1389.69,1514.69 U3.4 ; C5.1 1448.5,1411.5 1545,1315 2285,1315 TP4.1
Vin: C1.1 C3.1 C4.2 C7.2 C8.2 D2.1 J2.2 R2.2 R3.2 R6.1 R7.2 R15.2 R16.2 TP1.1 U1.9 U1.10 U1.11 U1.12 U1.13 U2.3 U3.2 | length 6820.8
  Top Layer w10: U2.3 C4.2@919.41,1664.41 ; U3.2 C7.2
  Top Layer w20: C4.2@919.41,1664.41 C4.2 925,1835 1070,1980 1325,1980 1345,1960 C8.2@1345,1876.5 ; 1170,170 2410,170 2485,245 2485,1750 ; R16.2 C8.2@1345,1876.5 ; C8.2 C8.2@1345,1876.5 ; C7.2 1720,1495 1750,1525 1750,1600 1791.5,1641.5 R15.2 1933.5,1750 2485,1750 ; R7.2 2473.5,776.5 ; C8.2@1345,1876.5 1432.99,1876.5 1581.5,2025 2380,2025 2485,1920 2485,1750
Vout: C10.1 J1.1 R1.2 TP2.1 U2.5 | length 899.2
  Top Layer w10: R1.2 832.91,1487.09 875,1445 930.32,1445 945,1430.32 U2.5
  Top Layer w80: J1.1 TP2.1
pads on no net: FID1.1 FID2.1 FID3.1 H9.0 H10.0 H11.0 H12.0 SH-J1.0 U4.3

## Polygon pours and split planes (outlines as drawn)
GND on Top Layer "TOP_LAYER_GND_P000" (solid, remove dead copper, pour order 0): 30,30 2770,30 2770,2470 30,2470
GND on Bottom Layer "BOTTOM_LAYER_GND_P002" (solid, remove dead copper, pour order 2): 30,30 2770,30 2770,2470 30,2470

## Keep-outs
Keep-Out Layer:
  text ".Layer_Name" at 577,-858.49 h60

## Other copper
Top Layer:
  rectangle net GND: 1550,1510 1620,1565
  rectangle net GND: 1550,1425 1620,1480
  region net Vin: 770,1040 620,1040 600,1020 600,150 620,130 1180,130 1200,150 1200,320 1180,340 910,340 890,360 890,790 830,850 830,1000 770,1000
  region net NetC2_1: 770,1055 620,1055 600,1075 600,1400 775,1400 775,1340 835,1340 835,1135 835,1095 770,1095
  region net GND: 1530,1500 1410,1500 1370,1460 1370,1445 1475,1445 1475,1480 1485,1490 1530,1490
  region net Vout: 815,1905 815,1510 775,1510 775,1450 600,1450 600,1880 670,1950 670,2155 cw(c712.5,2157.5) 710,2200 725,2200 cw(c725,2155) 770,2155 770,1950
  text ".Layer_Name" at 577,-858.49 h60
Bottom Layer:
  text ".Layer_Name" at 577,-858.49 h60

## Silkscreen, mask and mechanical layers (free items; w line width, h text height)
Top Overlay:
  text "'.PRJ_Number'.PCB_Rev-" at 1310,2380 h108.27
  text ".Layer_Name" at 577,-858.49 h60
Bottom Overlay:
  text ".Layer_Name" at 577,-858.49 h60
Top Paste:
  text ".Layer_Name" at 577,-858.49 h60
Bottom Paste:
  text ".Layer_Name" at 577,-858.49 h60
Top Solder:
  text ".Layer_Name" at 577,-858.49 h60
  text ".Layer_Name" at 577,-858.49 h60
Bottom Solder:
  text ".Layer_Name" at 577,-858.49 h60
Drill Guide:
  text ".Layer_Name" at 577,-858.49 h60
M1 Board Outline:
  the board outline again, w10
  text ".Layer_Name" at 577,-858.49 h60
M2 Board Dimensions:
  rectangle: 125,-400 500,-275
  rectangle: 0,-275 125,-150
  lines w7: 0,-275 1000,-275 ; 125,-400 125,-150 ; 250,-400 250,-150 ; 500,-400 500,-150 ; 750,-400 750,-150 ; 0,-400 0,-150 1000,-150 1000,-400 0,-400
  text ".Layer_Name" at 577,-858.49 h60
M3 3D STEP Top:
  text ".Layer_Name" at 577,-858.49 h60
M4 3D STEP Bottom:
  text ".Layer_Name" at 577,-858.49 h60
M5 Assembly Top:
  lines w10: -292,-930.17 6308,-930.17 ; -292,-726.83 6310,-726.83 ; -292,-523.5 -292,-1133.5 3713,-1133.5 6310,-1133.5 6310,-523.5 -291.5,-523.5 -291.5,-1133.5 1284,-1133.5 ; 2173,-1133.5 2173,-523.5 ; 3440,-726.83 3440,-523.5 ; 4280,-726.83 4280,-523.5 ; 4902,-1140 4902,-937.17
  text "COMPONENTS MARKED 'DNP' SHOULD NOT BE POPULATED." at 1153.5,-318.5 h60
  text "ASSEMBLY VARIANT:" at 1153,-434 h60
  text ".VariantName" at 2189,-434 h60
  text "PCB VIEWED FROM TOP SIDE" at -228.5,-655.67 h60
  text "BOARD #:" at 2248,-655.67 h60
  text ".PRJ_Number" at 2793.5,-655.67 h60
  text "REV:" at 3638,-655.67 h60
  text ".PCB_Rev" at 3929.5,-655.67 h60
  text "SVN REV:" at 4476,-655.67 h60
  text ".VersionControl_RevNumber" at 4982,-655.67 h60
  text "TID #:" at 2248,-859 h60
  text ".TID" at 2793.5,-859 h60
  text "PLOT NAME =" at -228.5,-1064.34 h60
  text ".plot_File_Name" at 577,-1064.34 h60
  text "GENERATED    :" at 2250,-1064.34 h60
  text ".Print_Date" at 3119.5,-1064.34 h60
  text ".Print_Time" at 3848.5,-1064.34 h60
  text "TEXAS INSTRUMENTS" at 5113,-1064.34 h60
M6 Assembly Bottom:
  lines w10: -292.5,-727.33 6309.5,-727.33 ; -290.5,-930.67 6309.5,-930.67 ; 1115.5,-1140.5 1115.5,-937.67 ; 1737.5,-727.33 1737.5,-524 ; 2577.5,-727.33 2577.5,-524 ; 3844.5,-1134 3844.5,-524 ; 4733.5,-1134 6309,-1134 6309,-524 -292.5,-524 -292.5,-1134 2304.5,-1134 6309.5,-1134 6309.5,-524
  text "COMPONENTS MARKED 'DNP' SHOULD NOT BE POPULATED." at 6102,-318 h60
  text ".VariantName" at 5058,-434 h60
  text "ASSEMBLY VARIANT:" at 6097,-434 h60
  text ".VersionControl_RevNumber" at 1035.5,-656.17 h60
  text "SVN REV:" at 1541.5,-656.17 h60
  text ".PCB_Rev" at 2088,-656.17 h60
  text "REV:" at 2379.5,-656.17 h60
  text ".PRJ_Number" at 3224,-656.17 h60
  text "BOARD #:" at 3769.5,-656.17 h60
  text "PCB VIEWED FROM BOTTOM SIDE" at 6246,-656.17 h60
  text ".TID" at 3224,-859.5 h60
  text "TID #:" at 3769.5,-859.5 h60
  text "TEXAS INSTRUMENTS" at 904.5,-1064.84 h60
  text ".Print_Time" at 2169,-1064.84 h60
  text ".Print_Date" at 2898,-1064.84 h60
  text "GENERATED    :" at 3767.5,-1064.84 h60
  text ".plot_File_Name" at 5440.5,-1064.84 h60
  text "PLOT NAME =" at 6246,-1064.84 h60
M9 Title Sheet:
  drawing of 57 lines, arcs and shapes, not listed
  text "1" at 739.84,8036.5 h70
  text "2" at 3235.5,8036.5 h70
  text "3" at 5724.84,8036.5 h70
  text "4" at 8231.51,8036.5 h70
  text "5" at 10730.5,8036.5 h70
  text "6" at 13235.5,8036.5 h70
  text "A" at -416.5,6893.5 h70
  text "A" at 14383.5,6893.5 h70
  text "B" at -416.5,4513.5 h70
  text "B" at 14383.5,4513.5 h70
  text "C" at -416.5,2138.5 h70
  text "C" at 14383.5,2138.5 h70
  text "PROJECT TITLE:" at 11343.5,277.5 h45
  text ".PRJ_Title" at 11393.5,144.17 h70
  text "DESIGNED FOR:" at 11343.5,-23.5 h45
  text ".PRJ_Customer" at 11393.5,-163.5 h70
  text "D" at -416.5,-231.5 h70
  text "D" at 14383.5,-231.5 h70
  text "FILE NAME:" at 11343.5,-323.5 h45
  text ".PCB_File_Name_No_Path" at 11393.5,-443.5 h70
  text "Texas Instruments (TI) and/or its licensors do not warrant the accuracy or completeness of this specification" at 6374,-605.34 h45
  text "ENGINEER:" at 11343.5,-613.5 h45
  text "LAYOUT BY:" at 12848.5,-613.5 h45
  text "or any information contained therein. TI and/or its licensors do not warrant that this design will meet" at 6329.01,-718 h45
  text ".PRJ_Engineer" at 11393.5,-768.49 h70
  text ".PCB_Layout" at 12899,-768.49 h70
  text "the specifications, will be suitable for your application or fit for any particular purpose, or will operate in" at 6329.01,-830.67 h45
  text ".Layer_Name" at 577,-858.49 h60
  text "ALTIUM DESIGNER VERSION:" at 12848.5,-923.5 h45
  text "an implementation. TI and/or its licensors do not warrant that the design is production worthy. You should" at 6329.01,-943.33 h45
  text "completely validate and test your design implementation to confirm the system functionality for your application." at 6374,-1056 h45
  text ".print_Scale" at 11393.5,-1056.83 h70
  text ".Application_BuildNumber" at 12899,-1056.83 h70
  text "1" at 739.84,-1263.5 h70
  text "2" at 3235.5,-1263.5 h70
  text "3" at 5724.84,-1263.5 h70
  text "4" at 8231.51,-1263.5 h70
  text "5" at 10730.5,-1263.5 h70
  text "6" at 13235.5,-1263.5 h70
M10 Fab Notes:
  drawing of 173 lines, arcs and shapes, not listed
  text "DESIGN INFORMATION" at 12378.02,6201 h60
  text "MIN. TRACK WIDTH:" at 11733.46,6021 h60
  text "8" at 12829.7,6021 h60
  text "MIL" at 12984.46,6021 h60
  text "MIN. CLEARANCE:" at 11733.46,5889 h60
  text "0.2" at 12769.7,5889 h60
  text "mm" at 12984.46,5889 h60
  text "MIN. VIA PAD SIZE:" at 11733.46,5757 h60
  text "24" at 12799.71,5757 h60
  text "MIL" at 12984.46,5757 h60
  text "0.05mm (2MIL)" at 12428.46,5615.29 h60
  text "MINIMUM ANNULAR RING" at 11404.23,5611 h60
  text "EXTERNAL" at 13136.46,5611 h60
  text "PER" at 11604.23,5493 h60
  text "IPC-D-275 CLASS 2 LEVEL C" at 11824.23,5493 h60
  text "MIL, HOLES" at 13312.46,5380.71 h60
  text "+/-" at 12920,5380 h60
  text "+/-" at 13774,5380 h60
  text "REGISTRATION TOLERANCES:" at 11404.23,5375 h60
  text "METAL" at 12604,5375 h60
  text "5" at 13180.2,5375 h60
  text "3" at 14013.2,5375 h60
  text "MIL" at 14129.46,5375 h60
  text "+/-" at 13774,5262 h60
  text "HOLE SIZE TOLERANCE (UNLESS OTHERWISE SPECIFIED):" at 11404.23,5257 h60
  text "3" at 14013.2,5257 h60
  text "MIL" at 14129.46,5257 h60
  text "MATERIAL:" at 11329.46,5047.54 h60
  text "FR-4 High Tg" at 12315.9,4907.21 h60
  text "FR-408" at 11750.46,4898.64 h60
  text "OTHER" at 13238.46,4898.64 h60
  text "X" at 12161,4895 h60
  text "62 MIL (1.6mm) +/-10%" at 12070.56,4735.92 h60
  text "THICKNESS:" at 11404.23,4731.64 h60
  text "X" at 11942.4,4731.64 h60
  text "OTHER" at 13355.46,4731.64 h60
  text "TOLERANCE:" at 11404.23,4573.64 h60
  text "X" at 12243.53,4573.64 h60
  text "ANSI IPC-6012 TYPE 3 CLASS 2" at 12430.48,4573.64 h60
  text "OTHER +/-" at 12430.46,4417.64 h60
  text "BOW & TWIST:" at 11404.23,4260.64 h60
  text "X" at 12243.53,4260.64 h60
  text "ANSI IPC-6012 TYPE 3 CLASS 2" at 12430.48,4260.64 h60
  text "OTHER +/-" at 12430.46,4102.13 h60
  text "DRILLING:" at 11329.46,3963.64 h60
  text "REFERENCE:" at 11404.23,3846.64 h60
  text "X" at 12052.46,3846.64 h60
  text "AS SHOWN" at 12239.46,3846.64 h60
  text "X" at 12953.46,3846.64 h60
  text "NC_DRILL FILES" at 13090.46,3846.64 h60
  text "PTH COPPER THICKNESS:" at 11404.23,3688.64 h60
  text "X" at 12534.46,3688.64 h60
  text "20-30 um" at 12671.46,3688.64 h60
  text "OTHER" at 13388.46,3688.64 h60
  text "BOARD FINISH:" at 11329.46,3529.64 h60
  text "SILKSCREEN:" at 11484.68,3411.64 h60
  text "X" at 12433.46,3411.64 h60
  text "TOP" at 12559.46,3411.64 h60
  text "X" at 12943.46,3411.64 h60
  text "BOTTOM" at 13070.46,3411.64 h60
  text "SILKSCREEN COLOR:" at 11484.68,3244.64 h60
  text "X" at 12432.42,3244.64 h60
  text "WHITE" at 12559.46,3244.64 h60
  text "OTHER" at 13070.46,3244.64 h60
  text "X" at 12563.42,3085.44 h60
  text "GREEN" at 12690.46,3085.44 h60
  text "OTHER" at 13308.46,3085.44 h60
  text "SOLDER RESIST COLOR:" at 11484.68,3074.64 h60
  text "X" at 12563.42,2915.44 h60
  text "MATTE" at 12690.46,2915.44 h60
  text "SEMI-GLOSS" at 13308,2914.8 h60
  text "IMMERSION GOLD (ENIG)" at 12390.46,2726.92 h60
  text "ENEPIG" at 13728,2723.64 h60
  text "SURFACE FINISH:" at 11329.46,2722.64 h60
  text "X" at 12203.51,2722.64 h60
  text "IMM. TIN/SILVER OR EQUIV" at 11659,2565.64 h60
  text "OTHER" at 13090.46,2565.64 h60
  text "ARRAY/PANEL:" at 11329.46,2386.64 h60
  text "CUT AND TRIM PER M1 BOARD OUTLINE" at 12390.46,2382.35 h60
  text "N.C. ROUTE" at 12390.46,2230.64 h60
  text "X" at 13069.46,2230.64 h60
  text "V. SCORE" at 13256.46,2230.64 h60
  text "CERTIFICATION:" at 11329.46,2093.64 h60
  text "MATERIALS AND WORKMANSHIP FOR ALL PCBS" at 12054.46,2093.64 h60
  text "TO MEET OR EXCEED THE REQUIREMENTS OF:" at 12054.46,1995.64 h60
  text "X" at 11680.96,1859.13 h60
  text "ANSI IPC-A-600F CLASS ->" at 11819.96,1859.13 h60
  text "X" at 13459.02,1859.13 h60
  text "2" at 13577.96,1859.14 h60
  text "1" at 13262.96,1857.64 h60
  text "3" at 13931.96,1857.64 h60
  text "X" at 12495.02,1699.64 h60
  text "RoHS" at 12631.96,1699.64 h60
  text "OTHER" at 13276.36,1699.64 h60
  text "PER ORDER" at 13673.42,1699.64 h60
  text "ALL BOARDS MUST MEET OR EXCEED UL94-V0 REQUIREMENTS." at 11357,1534 h60
  text "PCB MUST BEAR THE UL94V-0 UL REGISTERED MATERIAL ID NUMBER" at 11357,1414 h60
  text "ADDITIONAL REQUIREMENTS:" at 11329.46,1240.64 h60
  text "MICROSECTION:" at 11404.23,1125.64 h60
  text "YES" at 12309.96,1125.64 h60
  text "REQUIRED" at 13171.46,969.49 h60
  text "BARE BOARD ELEC. TEST:" at 11404.23,966.64 h60
  text "NONE" at 12709.96,966.64 h60
  text "X" at 13044.46,966.64 h60
  text "PER ORDER" at 13763.46,966.64 h60
  text ".Layer_Name" at 577,-858.49 h60
M11 Gerber Information:
  lines w10: -292,-930.17 6308,-930.17 ; -292,-726.83 6310,-726.83 ; -292,-523.5 -292,-1133.5 3713,-1133.5 6310,-1133.5 6310,-523.5 -291.5,-523.5 -291.5,-1133.5 1284,-1133.5 ; 2173,-1133.5 2173,-523.5 ; 3440,-726.83 3440,-523.5 ; 4280,-726.83 4280,-523.5 ; 4902,-1140 4902,-937.17
  text "ALL ARTWORK VIEWED FROM TOP SIDE" at -228.5,-655.67 h60
  text "BOARD #:" at 2248,-655.67 h60
  text ".PRJ_Number" at 2793.5,-655.67 h60
  text "REV:" at 3638,-655.67 h60
  text ".PCB_Rev" at 3929.5,-655.67 h60
  text "SVN REV:" at 4476,-655.67 h60
  text ".VersionControl_RevNumber" at 4982,-655.67 h60
  text "LAYER NAME =" at -228.5,-858.49 h60
  text "TID #:" at 2248,-859 h60
  text ".TID" at 2793.5,-859 h60
  text "PLOT NAME =" at -228.5,-1064.34 h60
  text ".plot_File_Name" at 577,-1064.34 h60
  text "GENERATED    :" at 2250,-1064.34 h60
  text ".Print_Date" at 3119.5,-1064.34 h60
  text ".Print_Time" at 3848.5,-1064.34 h60
  text "TEXAS INSTRUMENTS" at 5113,-1064.34 h60
M12 Stackup:
  drawing of 191 lines, arcs and shapes, not listed
  text "Layer" at 9797.84,7830 h60
  text "Name" at 10207.76,7830 h60
  text "Material" at 11137.5,7830 h60
  text "Thickness" at 11997.27,7830 h60
  text "Constant" at 12647.1,7830 h60
  text "Board Layer Stack" at 13216.96,7830 h60
  text "1" at 9797.84,7710 h60
  text "Top Overlay" at 10207.76,7710 h60
  text "2" at 9797.84,7590 h60
  text "Top Solder" at 10207.76,7590 h60
  text "Solder Resist" at 11137.5,7590 h60
  text "0.40mil" at 11997.27,7590 h60
  text "3.5" at 12647.1,7590 h60
  text "3" at 9797.84,7470 h60
  text "Top Layer" at 10207.76,7470 h60
  text "Copper" at 11137.5,7470 h60
  text "2.80mil" at 11997.27,7470 h60
  text "4" at 9797.84,7350 h60
  text "Dielectric1" at 10207.76,7350 h60
  text "FR-4" at 11137.5,7350 h60
  text "56.00mil" at 11997.27,7350 h60
  text "4.8" at 12647.1,7350 h60
  text "5" at 9797.84,7230 h60
  text "Bottom Layer" at 10207.76,7230 h60
  text "Copper" at 11137.5,7230 h60
  text "2.80mil" at 11997.27,7230 h60
  text "6" at 9797.84,7110 h60
  text "Bottom Solder" at 10207.76,7110 h60
  text "Solder Resist" at 11137.5,7110 h60
  text "0.40mil" at 11997.27,7110 h60
  text "3.5" at 12647.1,7110 h60
  text "7" at 9797.84,6990 h60
  text "Bottom Overlay" at 10207.76,6990 h60
  text ".Layer_Name" at 577,-858.49 h60
M13 Component Bodies Top:
  text ".Layer_Name" at 577,-858.49 h60
M14 Component Bodies Bottom:
  text ".Layer_Name" at 577,-858.49 h60
M15 Courtyards Top:
  text ".Layer_Name" at 577,-858.49 h60
M16 Courtyards Bottom:
  text ".Layer_Name" at 577,-858.49 h60
Drill Drawing:
  lines w10: 5336.09,2506.55 5349.9,2506.55 5349.9,2492.74 5377.53,2492.74 5377.53,2506.55 5391.34,2506.55 5391.34,2534.18 5377.53,2534.18 5377.53,2547.99 5349.9,2547.99 5349.9,2534.18 5336.09,2534.18 5336.09,2506.55 ; 5336.09,2630.87 5349.9,2630.87 5363.72,2617.06 5377.53,2630.87 5391.34,2630.87 5377.53,2644.68 5391.34,2658.5 5377.53,2658.5 5363.72,2672.31 5349.9,2658.5 5336.09,2658.5 5349.9,2644.68 5336.09,2630.87 ; 5336.09,2741.38 5391.34,2741.38 5391.34,2796.63 5336.09,2796.63 5336.09,2741.38 ; 5336.09,2865.7 5363.72,2879.51 5391.34,2865.7 5377.53,2893.32 5391.34,2920.95 5363.72,2907.14 5336.09,2920.95 5349.9,2893.32 5336.09,2865.7 ; 5336.09,2990.02 5336.09,3003.83 5349.9,3017.64 5336.09,3031.46 5336.09,3045.27 5349.9,3045.27 5363.72,3031.46 5377.53,3045.27 5391.34,3045.27 5391.34,3031.46 5377.53,3017.64 5391.34,3003.83 5391.34,2990.02 5377.53,2990.02 5363.72,3003.83 5349.9,2990.02 5336.09,2990.02 ; 5336.09,3141.96 5363.72,3114.34 5391.34,3141.96 5363.72,3169.59 5336.09,3141.96 ; 5336.09,3293.91 5391.34,3293.91 5363.72,3238.66 5336.09,3293.91
  lines w12: 5286,2455.44 8517.49,2455.44 ; 5286,3325.68 8517.49,3325.68 ; 5623.86,2331.12 5623.86,3450 ; 5955.86,2331.12 5955.86,3450 ; 6592.43,2331.12 6592.43,3450 ; 6851.57,2331.12 6851.57,3450 ; 7226.72,2331.12 7226.72,3450 ; 7951.05,2331.12 7951.05,3450 ; 5286,2331.12 8517.49,2331.12 8517.49,3450 5286,3450 5286,2331.12
  text "Symbol" at 5360.59,3362.98 h72
  text "Quantity" at 5661.16,3362.98 h72
  text "Finished Hole Size" at 5993.16,3362.98 h72
  text "Plated" at 6629.72,3362.98 h72
  text "Hole Type" at 6888.86,3362.98 h72
  text "Drill Layer Pair" at 7264.02,3362.98 h72
  text "Hole Tolerance" at 7988.35,3362.98 h72
  text "6" at 5661.16,3238.66 h60
  text "7.87mil (0.200mm)" at 5993.16,3238.66 h60
  text "PTH" at 6629.72,3238.66 h60
  text "Round" at 6888.86,3238.66 h60
  text "Top Layer - Bottom Layer" at 7264.02,3238.66 h60
  text "65" at 5661.16,3114.34 h60
  text "12.00mil (0.305mm)" at 5993.16,3114.34 h60
  text "PTH" at 6629.72,3114.34 h60
  text "Round" at 6888.86,3114.34 h60
  text "Top Layer - Bottom Layer" at 7264.02,3114.34 h60
  text "8" at 5661.16,2990.02 h60
  text "40.00mil (1.016mm)" at 5993.16,2990.02 h60
  text "PTH" at 6629.72,2990.02 h60
  text "Round" at 6888.86,2990.02 h60
  text "Top Layer - Bottom Layer" at 7264.02,2990.02 h60
  text "1" at 5661.16,2865.7 h60
  text "51.18mil (1.300mm)" at 5993.16,2865.7 h60
  text "PTH" at 6629.72,2865.7 h60
  text "Round" at 6888.86,2865.7 h60
  text "Top Layer - Bottom Layer" at 7264.02,2865.7 h60
  text "2" at 5661.16,2741.38 h60
  text "55.12mil (1.400mm)" at 5993.16,2741.38 h60
  text "PTH" at 6629.72,2741.38 h60
  text "Round" at 6888.86,2741.38 h60
  text "Top Layer - Bottom Layer" at 7264.02,2741.38 h60
  text "12" at 5661.16,2617.06 h60
  text "63.00mil (1.600mm)" at 5993.16,2617.06 h60
  text "PTH" at 6629.72,2617.06 h60
  text "Round" at 6888.86,2617.06 h60
  text "Top Layer - Bottom Layer" at 7264.02,2617.06 h60
  text "4" at 5661.16,2492.74 h60
  text "86.61mil (2.200mm)" at 5993.16,2492.74 h60
  text "PTH" at 6629.72,2492.74 h60
  text "Round" at 6888.86,2492.74 h60
  text "Top Layer - Bottom Layer" at 7264.02,2492.74 h60
  text "98 Total" at 5661.16,2368.42 h60
  text ".Layer_Name" at 577,-858.49 h60
M17 Embedded Cavity:
  text ".Layer_Name" at 577,-858.49 h60
M18 Embedded Assembly:
  text ".Layer_Name" at 577,-858.49 h60
M19 Embedded Keepout:
  text ".Layer_Name" at 577,-858.49 h60

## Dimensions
0,0 to 0,2500 on M2 Board Dimensions
0,0 to 2800,0 on M2 Board Dimensions
0,-400 to 1000,-400 on M2 Board Dimensions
